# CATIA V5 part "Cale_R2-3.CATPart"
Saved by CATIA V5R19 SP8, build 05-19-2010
Part number: Cale_R2-3
Nomenclature: 70_k
Bounding box of the stored display mesh (mm): x -5.5 to 5.5, y -5.491 to 5.491, z 0 to 0.2
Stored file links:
  C:\Users\rphgr\Desktop\0_Tapis_TC520B_vitesse\Cale_R2-3.CATPart
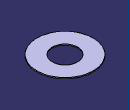
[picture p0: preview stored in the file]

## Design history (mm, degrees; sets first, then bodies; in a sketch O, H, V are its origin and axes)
Body1 (main body)
  AxisSystem1: origin (0, 0, 0), X (1, 0, 0), Y (0, 1, 0), Z (0, 0, 1)
  Sketch1 on XY plane of AxisSystem1, origin (0, 0, 0), H (1, 0, 0), V (0, 1, 0)
    circle A1 centre (0, 0) radius 2.5
    circle A2 centre (0, 0) radius 5.5
    radius A1 = 2.5
    radius A2 = 5.5
  Pad1: profile Sketch1, direction (0, 0, 1), length 0.2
